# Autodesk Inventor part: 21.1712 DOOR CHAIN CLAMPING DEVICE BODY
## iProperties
Created: 2007-05
Part Number: 21.1712 DOOR CHAIN CLAMPING DEVICE BODY
Document SubType Name: Modeling
Designer: Andy Moles
Material: Steel
Mass: 35.8863 g
Surface Area: 30.1643 cm^2
Volume: 4.5715 cm^3
Density: 7.85 g/cm^3
Author: Andy Moles
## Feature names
1. Base1
